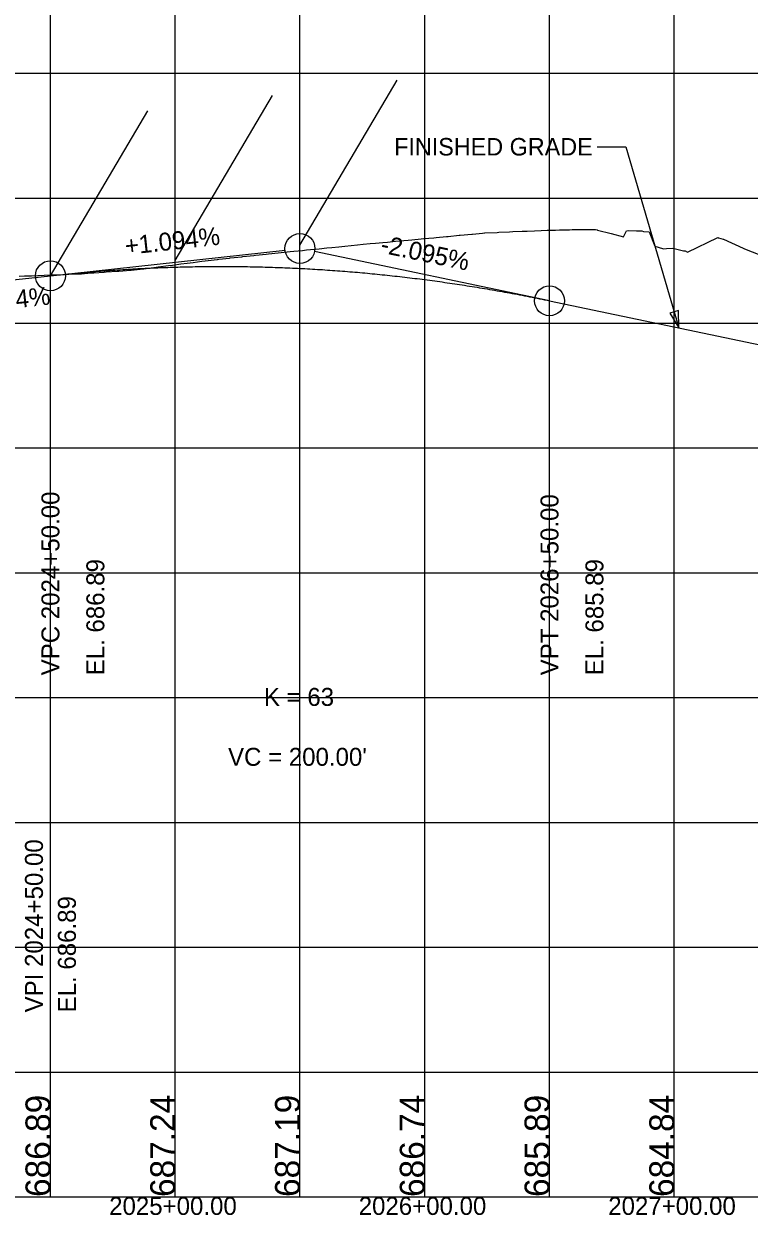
# Model space of a CAD drawing. Extents: x -7164 to 2214450, y -19642 to 253469.
# Drawn here: x 8439.3 to 8730, y -7.3 to 469.8 of the extents above; entities that cross this region are included whole.
import ezdxf

# ---------------------------------------------------------------- set-up
doc = ezdxf.new("R2010")
doc.units = 0
for name, color, linetype in [('DESIGN - PROFILE - Proposed', 7, 'Continuous'), ('DESIGN - PROFILE - Proposed Curve Text', 7, 'Continuous'), ('DESIGN - PROFILE - Proposed Text', 7, 'Continuous'), ('DESIGN - SCRATCH - User 1', 7, 'Continuous'), ('DESIGN - SHEET - Light Grid', 7, 'Continuous'), ('SURVEY - PROFILE - Ground Line with Text', 7, 'Continuous'), ('XTREE', 7, 'Continuous')]:
    doc.layers.add(name, color=color, linetype=linetype)

msp = doc.modelspace()

# ---------------------------------------------------------------- linework, layer by layer
at = {"layer": 'DESIGN - PROFILE - Proposed'}
for p, q in [((8400, 363.44), (8450, 368.91)), ((8400, 363.44), (8450, 368.91)), ((8650, 358.9), (8765, 334.8)), ((8650, 358.9), (8765, 334.8))]:
    msp.add_line(p, q, dxfattribs=at)
msp.add_spline([(8450, 368.91), (8454, 369.34), (8458, 369.74), (8462, 370.11), (8466, 370.46), (8470, 370.78), (8474, 371.08), (8478, 371.35), (8482, 371.6), (8486, 371.82), (8490, 372.01), (8494, 372.18), (8498, 372.33), (8502, 372.44), (8506, 372.54), (8510, 372.61), (8514, 372.65), (8518, 372.66), (8522, 372.66), (8526, 372.62), (8530, 372.56), (8534, 372.48), (8538, 372.36), (8542, 372.23), (8546, 372.07), (8550, 371.88), (8554, 371.67), (8558, 371.43), (8562, 371.16), (8566, 370.87), (8570, 370.56), (8574, 370.22), (8578, 369.85), (8582, 369.46), (8586, 369.04), (8590, 368.6), (8594, 368.13), (8598, 367.64), (8602, 367.12), (8606, 366.57), (8610, 366), (8614, 365.41), (8618, 364.79), (8622, 364.14), (8626, 363.47), (8630, 362.77), (8634, 362.05), (8638, 361.3), (8642, 360.52), (8646, 359.72), (8650, 358.9)], degree=3, dxfattribs=at)
msp.add_spline([(8450, 368.91), (8454, 369.34), (8458, 369.74), (8462, 370.11), (8466, 370.46), (8470, 370.78), (8474, 371.08), (8478, 371.35), (8482, 371.6), (8486, 371.82), (8490, 372.01), (8494, 372.18), (8498, 372.33), (8502, 372.44), (8506, 372.54), (8510, 372.61), (8514, 372.65), (8518, 372.66), (8522, 372.66), (8526, 372.62), (8530, 372.56), (8534, 372.48), (8538, 372.36), (8542, 372.23), (8546, 372.07), (8550, 371.88), (8554, 371.67), (8558, 371.43), (8562, 371.16), (8566, 370.87), (8570, 370.56), (8574, 370.22), (8578, 369.85), (8582, 369.46), (8586, 369.04), (8590, 368.6), (8594, 368.13), (8598, 367.64), (8602, 367.12), (8606, 366.57), (8610, 366), (8614, 365.41), (8618, 364.79), (8622, 364.14), (8626, 363.47), (8630, 362.77), (8634, 362.05), (8638, 361.3), (8642, 360.52), (8646, 359.72), (8650, 358.9)], degree=3, dxfattribs=at)
at = {"layer": 'DESIGN - PROFILE - Proposed Text'}
for p, q in [((8450, 368.91), (8544.04, 379.2)), ((8450, 368.91), (8544.04, 379.2)), ((8650, 358.9), (8555.87, 378.62)), ((8650, 358.9), (8555.87, 378.62))]:
    msp.add_line(p, q, dxfattribs=at)
msp.add_lwpolyline([(8669.04, 420.59), (8680.54, 420.59), (8701.85, 348.04)], dxfattribs=at)
msp.add_lwpolyline([(8669.04, 420.59), (8680.54, 420.59), (8701.85, 348.04)], dxfattribs=at)
msp.add_lwpolyline([(8698.2, 354.01), (8701.85, 348.04), (8701.68, 355.03)], close=True, dxfattribs=at)
msp.add_lwpolyline([(8698.2, 354.01), (8701.85, 348.04), (8701.68, 355.03)], close=True, dxfattribs=at)
for centre in [(8550, 379.85), (8550, 379.85), (8450, 368.91), (8450, 368.91), (8450, 368.91), (8450, 368.91), (8650, 358.9), (8650, 358.9)]:
    msp.add_circle(centre, 6, dxfattribs=at)
at = {"layer": 'DESIGN - SCRATCH - User 1'}
msp.add_line((6000, 0), (9700, 0), dxfattribs=at)
msp.add_line((6000, 0), (9700, 0), dxfattribs=at)
msp.add_lwpolyline([(6000, 0), (9178.68, 0), (9178.68, 1000)], dxfattribs=at)
msp.add_lwpolyline([(6000, 0), (9178.68, 0), (9178.68, 1000)], dxfattribs=at)
at = {"layer": 'DESIGN - SHEET - Light Grid'}
for p, q in [((8450, 0), (8450, 1000)), ((8450, 0), (8450, 1000)), ((8500, 0), (8500, 1000)), ((8500, 0), (8500, 1000)), ((8550, 0), (8550, 1000)), ((8550, 0), (8550, 1000)), ((8600, 0), (8600, 1000)), ((8600, 0), (8600, 1000)), ((8650, 0), (8650, 1000)), ((8650, 0), (8650, 1000)), ((8700, 0), (8700, 1000)), ((8700, 0), (8700, 1000)), ((6000, 450), (9700, 450)), ((6000, 450), (9700, 450)), ((6000, 400), (9700, 400)), ((6000, 400), (9700, 400)), ((6000, 350), (9700, 350)), ((6000, 350), (9700, 350)), ((6000, 300), (9700, 300)), ((6000, 300), (9700, 300)), ((6000, 250), (9700, 250)), ((6000, 250), (9700, 250)), ((6000, 200), (9700, 200)), ((6000, 200), (9700, 200)), ((6000, 150), (9700, 150)), ((6000, 150), (9700, 150)), ((6000, 100), (9700, 100)), ((6000, 100), (9700, 100)), ((6000, 50), (9700, 50)), ((6000, 50), (9700, 50)), ((6000, 0), (9300, 0)), ((6000, 0), (9300, 0))]:
    msp.add_line(p, q, dxfattribs=at)
at = {"layer": 'SURVEY - PROFILE - Ground Line with Text'}
for points in [[(8570.47, 381.02), (8573.03, 381.3), (8575.34, 381.52), (8578.12, 381.78), (8580.21, 381.98), (8583.22, 382.26), (8585.08, 382.43), (8588.32, 382.74), (8589.94, 382.89), (8593.42, 383.22), (8594.81, 383.35), (8598.52, 383.69), (8599.67, 383.8), (8603.62, 384.17), (8604.54, 384.26), (8608.72, 384.65), (8609.4, 384.7), (8613.82, 385.12), (8614.26, 385.16), (8618.92, 385.6), (8619.12, 385.62), (8623.09, 386), (8624.01, 386.08), (8624.12, 386.08), (8629.01, 386.28), (8629.75, 386.32), (8634.02, 386.51), (8635.37, 386.59), (8639.02, 386.76), (8641.03, 386.82), (8644.03, 386.95), (8646.7, 387.03), (8649.03, 387.12), (8652.4, 387.22), (8654.03, 387.28), (8657.99, 387.33), (8659.04, 387.4), (8663.56, 387.42), (8664.05, 387.45), (8668.48, 387.45), (8669.05, 387.29), (8669.06, 387.28), (8669.17, 387.25), (8674.66, 385.82), (8679.6, 384.53), (8680.83, 386.88), (8681.81, 387.02), (8684.85, 386.93), (8685.53, 386.92), (8686.98, 386.9), (8687.62, 386.61), (8689.97, 386.53), (8692.15, 380.76), (8695.31, 379.8), (8695.75, 379.69), (8696.95, 379.84), (8699.42, 379.92), (8703.67, 378.96), (8704.42, 378.89), (8705.27, 378.35), (8717.5, 384.25), (8717.6, 384.17), (8717.72, 384.08), (8719.64, 383.63), (8719.76, 383.53), (8727.67, 380.03), (8728.08, 379.69), (8728.1, 379.68), (8737.38, 376.07)], [(8570.47, 381.02), (8573.03, 381.3), (8575.34, 381.52), (8578.12, 381.78), (8580.21, 381.98), (8583.22, 382.26), (8585.08, 382.43), (8588.32, 382.74), (8589.94, 382.89), (8593.42, 383.22), (8594.81, 383.35), (8598.52, 383.69), (8599.67, 383.8), (8603.62, 384.17), (8604.54, 384.26), (8608.72, 384.65), (8609.4, 384.7), (8613.82, 385.12), (8614.26, 385.16), (8618.92, 385.6), (8619.12, 385.62), (8623.09, 386), (8624.01, 386.08), (8624.12, 386.08), (8629.01, 386.28), (8629.75, 386.32), (8634.02, 386.51), (8635.37, 386.59), (8639.02, 386.76), (8641.03, 386.82), (8644.03, 386.95), (8646.7, 387.03), (8649.03, 387.12), (8652.4, 387.22), (8654.03, 387.28), (8657.99, 387.33), (8659.04, 387.4), (8663.56, 387.42), (8664.05, 387.45), (8668.48, 387.45), (8669.05, 387.29), (8669.06, 387.28), (8669.17, 387.25), (8674.66, 385.82), (8679.6, 384.53), (8680.83, 386.88), (8681.81, 387.02), (8684.85, 386.93), (8685.53, 386.92), (8686.98, 386.9), (8687.62, 386.61), (8689.97, 386.53), (8692.15, 380.76), (8695.31, 379.8), (8695.75, 379.69), (8696.95, 379.84), (8699.42, 379.92), (8703.67, 378.96), (8704.42, 378.89), (8705.27, 378.35), (8717.5, 384.25), (8717.6, 384.17), (8717.72, 384.08), (8719.64, 383.63), (8719.76, 383.53), (8727.67, 380.03), (8728.08, 379.69), (8728.1, 379.68), (8737.38, 376.07)], [(8570.47, 381.02), (8573.03, 381.3), (8575.34, 381.52), (8578.12, 381.78), (8580.21, 381.98), (8583.22, 382.26), (8585.08, 382.43), (8588.32, 382.74), (8589.94, 382.89), (8593.42, 383.22), (8594.81, 383.35), (8598.52, 383.69), (8599.67, 383.8), (8603.62, 384.17), (8604.54, 384.26), (8608.72, 384.65), (8609.4, 384.7), (8613.82, 385.12), (8614.26, 385.16), (8618.92, 385.6), (8619.12, 385.62), (8623.09, 386), (8624.01, 386.08), (8624.12, 386.08), (8629.01, 386.28), (8629.75, 386.32), (8634.02, 386.51), (8635.37, 386.59), (8639.02, 386.76), (8641.03, 386.82), (8644.03, 386.95), (8646.7, 387.03), (8649.03, 387.12), (8652.4, 387.22), (8654.03, 387.28), (8657.99, 387.33), (8659.04, 387.4), (8663.56, 387.42), (8664.05, 387.45), (8668.48, 387.45), (8669.05, 387.29), (8669.06, 387.28), (8669.17, 387.25), (8674.66, 385.82), (8679.6, 384.53), (8680.83, 386.88), (8681.81, 387.02), (8684.85, 386.93), (8685.53, 386.92), (8686.98, 386.9), (8687.62, 386.61), (8689.97, 386.53), (8692.15, 380.76), (8695.31, 379.8), (8695.75, 379.69), (8696.95, 379.84), (8699.42, 379.92), (8703.67, 378.96), (8704.42, 378.89), (8705.27, 378.35), (8717.5, 384.25), (8717.6, 384.17), (8717.72, 384.08), (8719.64, 383.63), (8719.76, 383.53), (8727.67, 380.03), (8728.08, 379.69), (8728.1, 379.68), (8737.38, 376.07)], [(8570.47, 381.02), (8573.03, 381.3), (8575.34, 381.52), (8578.12, 381.78), (8580.21, 381.98), (8583.22, 382.26), (8585.08, 382.43), (8588.32, 382.74), (8589.94, 382.89), (8593.42, 383.22), (8594.81, 383.35), (8598.52, 383.69), (8599.67, 383.8), (8603.62, 384.17), (8604.54, 384.26), (8608.72, 384.65), (8609.4, 384.7), (8613.82, 385.12), (8614.26, 385.16), (8618.92, 385.6), (8619.12, 385.62), (8623.09, 386), (8624.01, 386.08), (8624.12, 386.08), (8629.01, 386.28), (8629.75, 386.32), (8634.02, 386.51), (8635.37, 386.59), (8639.02, 386.76), (8641.03, 386.82), (8644.03, 386.95), (8646.7, 387.03), (8649.03, 387.12), (8652.4, 387.22), (8654.03, 387.28), (8657.99, 387.33), (8659.04, 387.4), (8663.56, 387.42), (8664.05, 387.45), (8668.48, 387.45), (8669.05, 387.29), (8669.06, 387.28), (8669.17, 387.25), (8674.66, 385.82), (8679.6, 384.53), (8680.83, 386.88), (8681.81, 387.02), (8684.85, 386.93), (8685.53, 386.92), (8686.98, 386.9), (8687.62, 386.61), (8689.97, 386.53), (8692.15, 380.76), (8695.31, 379.8), (8695.75, 379.69), (8696.95, 379.84), (8699.42, 379.92), (8703.67, 378.96), (8704.42, 378.89), (8705.27, 378.35), (8717.5, 384.25), (8717.6, 384.17), (8717.72, 384.08), (8719.64, 383.63), (8719.76, 383.53), (8727.67, 380.03), (8728.08, 379.69), (8728.1, 379.68), (8737.38, 376.07)], [(8437.43, 368.77), (8439.63, 368.87), (8442.43, 368.92), (8444.94, 369.04), (8447.43, 369.11), (8450.26, 369.25), (8452.42, 369.31), (8455.6, 369.47), (8457.41, 369.52), (8460.95, 369.71), (8462.39, 369.76), (8466.24, 370.05), (8467.4, 370.08), (8471.53, 370.41), (8472.38, 370.45), (8476.81, 370.8), (8477.39, 370.83), (8482.11, 371.22), (8482.39, 371.23), (8487.22, 371.64), (8487.39, 371.67), (8487.43, 371.67), (8492.36, 372.35), (8493.11, 372.44), (8497.3, 373.01), (8498.87, 373.21), (8502.24, 373.66), (8504.73, 373.97), (8507.16, 374.29), (8510.7, 374.72), (8512.07, 374.9), (8516.82, 375.47), (8516.96, 375.49), (8517.48, 375.55), (8521.82, 376.02), (8522.03, 376.04), (8526.68, 376.54), (8527.13, 376.59), (8531.53, 377.06), (8532.23, 377.14), (8536.39, 377.59), (8537.34, 377.69), (8541.25, 378.11), (8542.44, 378.24), (8546.11, 378.63), (8547.54, 378.79), (8550.99, 379.1), (8552.63, 379.27), (8555.86, 379.57), (8557.73, 379.77), (8560.73, 380.05), (8562.83, 380.27), (8565.6, 380.53), (8567.93, 380.78), (8570.47, 381.02)], [(8437.43, 368.77), (8439.63, 368.87), (8442.43, 368.92), (8444.94, 369.04), (8447.43, 369.11), (8450.26, 369.25), (8452.42, 369.31), (8455.6, 369.47), (8457.41, 369.52), (8460.95, 369.71), (8462.39, 369.76), (8466.24, 370.05), (8467.4, 370.08), (8471.53, 370.41), (8472.38, 370.45), (8476.81, 370.8), (8477.39, 370.83), (8482.11, 371.22), (8482.39, 371.23), (8487.22, 371.64), (8487.39, 371.67), (8487.43, 371.67), (8492.36, 372.35), (8493.11, 372.44), (8497.3, 373.01), (8498.87, 373.21), (8502.24, 373.66), (8504.73, 373.97), (8507.16, 374.29), (8510.7, 374.72), (8512.07, 374.9), (8516.82, 375.47), (8516.96, 375.49), (8517.48, 375.55), (8521.82, 376.02), (8522.03, 376.04), (8526.68, 376.54), (8527.13, 376.59), (8531.53, 377.06), (8532.23, 377.14), (8536.39, 377.59), (8537.34, 377.69), (8541.25, 378.11), (8542.44, 378.24), (8546.11, 378.63), (8547.54, 378.79), (8550.99, 379.1), (8552.63, 379.27), (8555.86, 379.57), (8557.73, 379.77), (8560.73, 380.05), (8562.83, 380.27), (8565.6, 380.53), (8567.93, 380.78), (8570.47, 381.02)], [(8437.43, 368.77), (8439.63, 368.87), (8442.43, 368.92), (8444.94, 369.04), (8447.43, 369.11), (8450.26, 369.25), (8452.42, 369.31), (8455.6, 369.47), (8457.41, 369.52), (8460.95, 369.71), (8462.39, 369.76), (8466.24, 370.05), (8467.4, 370.08), (8471.53, 370.41), (8472.38, 370.45), (8476.81, 370.8), (8477.39, 370.83), (8482.11, 371.22), (8482.39, 371.23), (8487.22, 371.64), (8487.39, 371.67), (8487.43, 371.67), (8492.36, 372.35), (8493.11, 372.44), (8497.3, 373.01), (8498.87, 373.21), (8502.24, 373.66), (8504.73, 373.97), (8507.16, 374.29), (8510.7, 374.72), (8512.07, 374.9), (8516.82, 375.47), (8516.96, 375.49), (8517.48, 375.55), (8521.82, 376.02), (8522.03, 376.04), (8526.68, 376.54), (8527.13, 376.59), (8531.53, 377.06), (8532.23, 377.14), (8536.39, 377.59), (8537.34, 377.69), (8541.25, 378.11), (8542.44, 378.24), (8546.11, 378.63), (8547.54, 378.79), (8550.99, 379.1), (8552.63, 379.27), (8555.86, 379.57), (8557.73, 379.77), (8560.73, 380.05), (8562.83, 380.27), (8565.6, 380.53), (8567.93, 380.78), (8570.47, 381.02)], [(8437.43, 368.77), (8439.63, 368.87), (8442.43, 368.92), (8444.94, 369.04), (8447.43, 369.11), (8450.26, 369.25), (8452.42, 369.31), (8455.6, 369.47), (8457.41, 369.52), (8460.95, 369.71), (8462.39, 369.76), (8466.24, 370.05), (8467.4, 370.08), (8471.53, 370.41), (8472.38, 370.45), (8476.81, 370.8), (8477.39, 370.83), (8482.11, 371.22), (8482.39, 371.23), (8487.22, 371.64), (8487.39, 371.67), (8487.43, 371.67), (8492.36, 372.35), (8493.11, 372.44), (8497.3, 373.01), (8498.87, 373.21), (8502.24, 373.66), (8504.73, 373.97), (8507.16, 374.29), (8510.7, 374.72), (8512.07, 374.9), (8516.82, 375.47), (8516.96, 375.49), (8517.48, 375.55), (8521.82, 376.02), (8522.03, 376.04), (8526.68, 376.54), (8527.13, 376.59), (8531.53, 377.06), (8532.23, 377.14), (8536.39, 377.59), (8537.34, 377.69), (8541.25, 378.11), (8542.44, 378.24), (8546.11, 378.63), (8547.54, 378.79), (8550.99, 379.1), (8552.63, 379.27), (8555.86, 379.57), (8557.73, 379.77), (8560.73, 380.05), (8562.83, 380.27), (8565.6, 380.53), (8567.93, 380.78), (8570.47, 381.02)]]:
    msp.add_lwpolyline(points, dxfattribs=at)
at = {"layer": 'XTREE'}
for p, q in [((8550, 381.17), (8588.97, 447.24)), ((8550, 381.17), (8588.97, 447.24)), ((8500, 375.01), (8538.97, 441.08)), ((8500, 375.01), (8538.97, 441.08)), ((8450, 368.91), (8488.97, 434.98)), ((8450, 368.91), (8488.97, 434.98))]:
    msp.add_line(p, q, dxfattribs=at)

# ---------------------------------------------------------------- texts
at = {"layer": 'DESIGN - PROFILE - Proposed Curve Text'}
for s, p in [('K = 63', (8535.55, 196.66)), ('K = 63', (8535.55, 196.66)), ("VC = 200.00'", (8521.18, 172.66)), ("VC = 200.00'", (8521.18, 172.66))]:
    msp.add_text(s, height=7.2, dxfattribs=at).set_placement(p)
for s, p in [('VPI 2024+50.00', (8447, 73.91)), ('VPI 2024+50.00', (8447, 73.91)), ('EL. 686.89', (8460.2, 73.91)), ('EL. 686.89', (8460.2, 73.91))]:
    msp.add_text(s, height=7.2, rotation=90, dxfattribs=at).set_placement(p)
at = {"layer": 'DESIGN - PROFILE - Proposed Text'}
for s, height, p in [('FINISHED GRADE', 7, (8587.74, 417.09)), ('FINISHED GRADE', 7, (8587.74, 417.09)), ('2025+00.00', 7.2, (8473.54, -7.2)), ('2025+00.00', 7.2, (8473.54, -7.2)), ('2026+00.00', 7.2, (8573.54, -7.2)), ('2026+00.00', 7.2, (8573.54, -7.2)), ('2027+00.00', 7.2, (8673.54, -7.2)), ('2027+00.00', 7.2, (8673.54, -7.2))]:
    msp.add_text(s, height=height, dxfattribs=at).set_placement(p)
for s, height, rotation, p in [('+1.094%', 7.2, 6.2433, (8480.19, 377.24)), ('+1.094%', 7.2, 6.2433, (8480.19, 377.24)), ('-2.095%', 7.2, 348.166, (8581.94, 378.27)), ('-2.095%', 7.2, 348.166, (8581.94, 378.27)), ('+1.094%', 7.2, 6.2433, (8412.17, 353.29)), ('+1.094%', 7.2, 6.2433, (8412.17, 353.29)), ('VPC 2024+50.00 ', 7.2, 90, (8453.6, 208.9)), ('VPC 2024+50.00 ', 7.2, 90, (8453.6, 208.9)), ('VPT 2026+50.00 ', 7.2, 90, (8653.6, 208.9)), ('VPT 2026+50.00 ', 7.2, 90, (8653.6, 208.9)), ('EL. 686.89', 7.2, 90, (8471.6, 208.9)), ('EL. 686.89', 7.2, 90, (8471.6, 208.9)), ('EL. 685.89', 7.2, 90, (8671.6, 208.9)), ('EL. 685.89', 7.2, 90, (8671.6, 208.9)), ('686.89', 10, 90, (8450, 0)), ('686.89', 10, 90, (8450, 0)), ('687.24', 10, 90, (8500, 0)), ('687.24', 10, 90, (8500, 0)), ('687.19', 10, 90, (8550, 0)), ('687.19', 10, 90, (8550, 0)), ('686.74', 10, 90, (8600, 0)), ('686.74', 10, 90, (8600, 0)), ('685.89', 10, 90, (8650, 0)), ('685.89', 10, 90, (8650, 0)), ('684.84', 10, 90, (8700, 0)), ('684.84', 10, 90, (8700, 0))]:
    msp.add_text(s, height=height, rotation=rotation, dxfattribs=at).set_placement(p)

doc.saveas('drawing.dxf')
